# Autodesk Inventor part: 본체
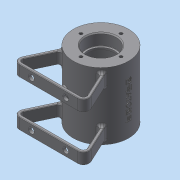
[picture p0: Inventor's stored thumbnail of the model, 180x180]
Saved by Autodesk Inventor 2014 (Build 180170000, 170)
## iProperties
Created: 2021-12
Part Number: 본체
Material: 일반
Document SubType Name: Modeling
Designer: dg
Density: 1 g/cm^3
Appearance: 기본값
Author: dg
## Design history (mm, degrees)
sketch "스케치1"
  geometry: C1 r 29 at (0, 0); 1 further point
  constraints: 1 centre point, 1 coincident
  dimensions: "d0" = 58 diameter of C1
extrude "돌출1" new body sketch "스케치1" stored distance "d1" = 70; taper "d2" = 0 deg
node "작업 평면1"
sketch "스케치2"
  geometry: C1 r 5 at (0, 0); 1 further point
  constraints: 1 centre point, 1 coincident
  dimensions: "d4" = 10 diameter of C1
extrude "돌출2" join sketch "스케치2" stored distance "d5" = 70; taper "d6" = 0 deg
sketch "스케치3"
  geometry: L1 (0, 0)-(-10.945, -30.07); L2 (0, 0)-(0, -42.067)
  constraints: 4 end point, 1 vertical
  dimensions: "d7" = 20 deg angle of L2 L1; "d8" = 32 distance of L1.start L1.end
node "작업 평면2"
sketch "스케치4"
  geometry: C1 r 6 at (0, 0); 1 further point
  constraints: 1 centre point, 1 coincident
  dimensions: "d9" = 12 diameter of C1
extrude "돌출3" join sketch "스케치4" stored distance "d10" = 70; taper "d11" = 0 deg
node "작업 평면3"
sketch "스케치6"
  geometry: L1 (-22.743, -17.993)-(-40, -55); L2 (-40, -55)-(40, -55); L3 (40, -55)-(22.743, -17.993); L4 (-20.574, -20.438)-(-35.291, -52); L5 (-35.291, -52)-(35.291, -52); L6 (35.291, -52)-(20.574, -20.438); A1 r 29 centre (0, 0) between (-22.743, -17.993) and (22.743, -17.993) reference; 1 further point
  constraints: 12 end point, 4 point on circle, 1 horizontal
  dimensions: "d13" = 80 distance of L1.end L2.end; "d14" = 40 horizontal distance of point (0, 0) L1.end; "d15" = 55 distance from line of point (0, 0) L2; "d16" = 65 deg angle of L2 L1; "d17" = 65 deg angle of L2 L3; "d18" = 3 distance between parallel lines of L1 L4; "d19" = 3 distance between parallel lines of L3 L6; "d20" = 3 distance between parallel lines of L2 L5
extrude "돌출4" join sketch "스케치6" distance "d21" = 12; taper "d22" = 0 deg
fillet "모깎기1" dims "d23" = 6
fillet "모깎기2" dims "d24" = 3
fillet "모깎기3" dims "d25" = 0.5
fillet "모깎기4" dims "d26" = 3
sketch "스케치7"
  geometry: L1 (0, -11.5)-(61.164, -11.5) reference; C1 r 3 at (12.582, -5.5); C2 r 3 at (48.582, -5.5); 1 further point
  constraints: 2 centre point, 1 equal radius, 1 horizontal alignment
  dimensions: "d27" = 36 distance of C2.centre C1.centre; "d28" = 18 horizontal distance of C1.centre point (30.582, 18.5); "d29" = 6 distance from line of L1 C1.centre; "d30" = 6 diameter of C1
extrude "돌출5" cut sketch "스케치7" stored distance "d31" = 12; taper "d32" = 0 deg
sketch "스케치8"
  geometry: L1 (29, 35)-(-29, 35) reference; L2 (-29, -35)-(29, -35) reference; L3 (0, 35)-(0, -35); L4 (0, 35)-(16, 35); L5 (16, 35)-(16, 23); L6 (16, 23)-(14, 23); L7 (14, 23)-(14, 21); L8 (14, 21)-(21, 21); L9 (21, 21)-(21, -21); L10 (21, -21)-(14, -21); L11 (14, -21)-(14, -23); L12 (14, -23)-(16, -23); L13 (16, -23)-(16, -35); L14 (16, -35)-(0, -35); 1 further point
  constraints: 24 end point, 6 parallel, 3 perpendicular, 2 midpoint, 2 point on line, 1 collinear
  dimensions: "d33" = 32 diameter of L5 L3; "d34" = 28 diameter of L7 L3; "d35" = 12 distance of L4.end L5.end; "d36" = 42 distance of L8.end L9.end; "d37" = 2 distance between parallel lines of L12 L10; "d38" = 12 distance of L12.end L13.end; "d39" = 42 diameter of L9 L3; "d40" = 28 diameter of L11 L3; "d41" = 32 diameter of L13 L3
revolve "회전1" sketch "스케치8" stored, may be unused: angle "d42" = 90 deg
hole "구멍1" diameter "d45" = 3; stored, may be unused: countersink angle "d49" = 90 deg, drill point angle "d51" = 118 deg; dims "d43" = 10, "d44" = 10, "d46" = 6, "d47" = 4, "d48" = 2, "d50" = 8
hole "구멍2" diameter "d54" = 5.188; stored, may be unused: countersink angle "d58" = 90 deg, drill point angle "d60" = 118 deg; dims "d52" = 10, "d53" = 10, "d55" = 6, "d56" = 4, "d57" = 2, "d59" = 8
hole "구멍3" diameter "d63" = 5.188; stored, may be unused: countersink angle "d67" = 90 deg, drill point angle "d69" = 118 deg; dims "d61" = 10, "d62" = 10, "d64" = 100, "d65" = 4, "d66" = 2, "d68" = 8
fillet "모깎기5" dims "d70" = 1, "d71" = 0.3, "d72" = 3
chamfer "모따기1" distance "d73" = 1; stored, may be unused: second distance "d74" = 2, angle "d75" = 45 deg
sketch "스케치9"
  geometry: C1 r 29 at (0, 0) reference; 1 further point
  constraints: 1 vertical alignment
  dimensions: "d76" = 21 distance of C1.centre point (0, 21)
hole "구멍4" sketch "스케치9" at (0, 21) diameter "d77" = 3.242; stored, may be unused: countersink angle "d81" = 90 deg, drill point angle "d83" = 118 deg; dims "d78" = 8, "d79" = 4, "d80" = 2, "d82" = 10
node "작업 평면4"
sketch "스케치10"
  geometry: L1 (29, 35)-(-29, 35) reference; L2 (29, -35)-(29, 35) reference; 2 further points
  constraints: 2 coincident, 1 other
  dimensions: "d91" = 29 distance from line of L2 point (0, 0) (derived); "d92" = 35 distance from line of L1 point (0, 0) (derived)
feature "엠보싱1" sketch "스케치10" dims "d2" = 0, "d13" = 80, "d14" = 40, "d15" = 55, "d16" = 65 deg, "d17" = 65 deg, "d18" = 3, "d19" = 3, "d20" = 3, "d89" = 0.5, "d90" = 0
node "솔리드1"
mirror "대칭1"
pattern_circular "원형 패턴1" dims angle "d85" = 360 deg
mirror "대칭2"
node "투영된 루프1"
other parameters: "d3" = 32, "d12" = 18
